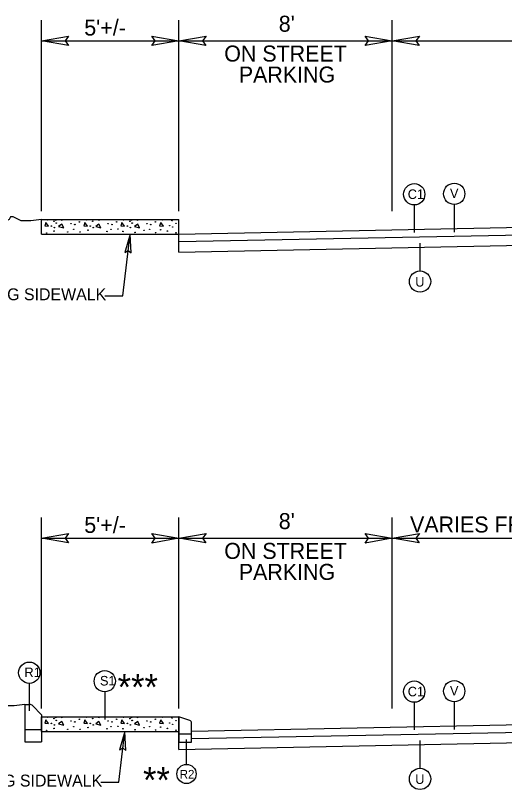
# Model space of a CAD drawing. Extents: x 1022283 to 1026986, y 174822 to 180471.
# Drawn here: x 1023136 to 1023625, y 178950 to 179724 of the extents above; entities that cross this region are included whole.
import ezdxf

# ---------------------------------------------------------------- set-up
doc = ezdxf.new("R2010")
doc.units = 0
for name, color, linetype in [('Default', 7, 'Continuous'), ('Prop Dimension', 7, 'Continuous'), ('Prop Terminator CELL', 7, 'Continuous'), ('Typical Curb CELL', 7, 'Continuous'), ('Typical ID Circle CELL', 7, 'Continuous'), ('Typical Slope Point Local CELL', 7, 'Continuous'), ('Typical Text General CELL', 7, 'Continuous'), ('Typical Text ID Circle CELL', 7, 'Continuous')]:
    doc.layers.add(name, color=color, linetype=linetype)

# ---------------------------------------------------------------- blocks, each defined once
blk = doc.blocks.new('Terminator')
at = {"layer": 'Prop Terminator CELL'}
blk.add_lwpolyline([(-9, 1.55), (0, 0), (-9.05, -1.6), (-7.9, 0)], close=True, dxfattribs=at)

msp = doc.modelspace()

# ---------------------------------------------------------------- linework, layer by layer
at = {"layer": 'Default'}
for p, q in [((1023162.42, 179527.88), (1023162.42, 179718.7)), ((1023299.79, 179527.88), (1023299.79, 179718.7)), ((1023512.98, 179527.88), (1023512.98, 179718.7)), ((1023162.42, 179698.14), (1023299.79, 179698.14)), ((1023162.42, 179698.14), (1023299.79, 179698.14)), ((1023299.79, 179698.14), (1023807.5, 179698.14)), ((1023162.42, 179527.88), (1023162.42, 179683.89)), ((1023162.42, 179527.88), (1023162.42, 179683.89)), ((1023162.42, 179030.88), (1023162.42, 179221.7)), ((1023299.79, 179030.88), (1023299.79, 179221.7)), ((1023512.98, 179030.88), (1023512.98, 179221.7)), ((1023162.42, 179201.13), (1023299.79, 179201.13)), ((1023162.42, 179201.13), (1023299.79, 179201.13)), ((1023299.79, 179201.13), (1023807.5, 179201.13)), ((1023162.42, 179030.88), (1023162.42, 179186.89)), ((1023162.42, 179030.88), (1023162.42, 179186.89))]:
    msp.add_line(p, q, dxfattribs=at)
at = {"layer": 'Prop Dimension'}
for p, q in [((1023299.79, 179505.09), (1023807.5, 179515.24)), ((1023299.79, 179505.09), (1023807.5, 179515.24)), ((1023299.79, 179497.58), (1023807.5, 179507.74)), ((1023299.79, 179497.58), (1023807.5, 179507.74)), ((1023243.88, 179443.37), (1023251.01, 179505.09)), ((1023299.79, 179487), (1023807.5, 179497.16)), ((1023225.73, 179443.37), (1023243.88, 179443.37)), ((1023312.45, 179008.34), (1023807.5, 179018.24)), ((1023312.45, 179008.34), (1023807.5, 179018.24)), ((1023312.45, 179000.84), (1023807.5, 179010.74)), ((1023312.45, 179000.84), (1023807.5, 179010.74)), ((1023239.83, 178957.41), (1023245.68, 179008.08)), ((1023299.79, 178990), (1023807.5, 179000.15)), ((1023221.68, 178957.41), (1023239.83, 178957.41))]:
    msp.add_line(p, q, dxfattribs=at)
at = {"layer": 'Prop Terminator CELL'}
for points in [[(1023189.42, 179693.49), (1023162.42, 179698.14), (1023189.57, 179702.94), (1023186.12, 179698.14)], [(1023189.42, 179693.49), (1023162.42, 179698.14), (1023189.57, 179702.94), (1023186.12, 179698.14)], [(1023272.79, 179702.79), (1023299.79, 179698.14), (1023272.64, 179693.34), (1023276.09, 179698.14)], [(1023272.79, 179702.79), (1023299.79, 179698.14), (1023272.64, 179693.34), (1023276.09, 179698.14)], [(1023326.79, 179693.49), (1023299.79, 179698.14), (1023326.94, 179702.94), (1023323.49, 179698.14)], [(1023485.98, 179702.79), (1023512.98, 179698.14), (1023485.83, 179693.34), (1023489.28, 179698.14)], [(1023539.98, 179693.49), (1023512.98, 179698.14), (1023540.13, 179702.94), (1023536.68, 179698.14)], [(1023189.42, 179196.48), (1023162.42, 179201.13), (1023189.57, 179205.93), (1023186.12, 179201.13)], [(1023189.42, 179196.48), (1023162.42, 179201.13), (1023189.57, 179205.93), (1023186.12, 179201.13)], [(1023272.79, 179205.78), (1023299.79, 179201.13), (1023272.64, 179196.33), (1023276.09, 179201.13)], [(1023272.79, 179205.78), (1023299.79, 179201.13), (1023272.64, 179196.33), (1023276.09, 179201.13)], [(1023326.79, 179196.48), (1023299.79, 179201.13), (1023326.94, 179205.93), (1023323.49, 179201.13)], [(1023485.98, 179205.78), (1023512.98, 179201.13), (1023485.83, 179196.33), (1023489.28, 179201.13)], [(1023539.98, 179196.48), (1023512.98, 179201.13), (1023540.13, 179205.93), (1023536.68, 179201.13)]]:
    msp.add_lwpolyline(points, close=True, dxfattribs=at)
at = {"layer": 'Typical Curb CELL'}
for p, q in [((1023162.42, 179519.61), (1023299.79, 179519.61)), ((1023162.42, 179505.09), (1023162.42, 179519.61)), ((1023162.42, 179519.61), (1023299.79, 179519.61)), ((1023162.42, 179505.09), (1023162.42, 179519.61)), ((1023166.92, 179516.7), (1023165.86, 179513.18)), ((1023166.92, 179516.7), (1023165.86, 179513.18)), ((1023169.57, 179512.98), (1023166.92, 179516.7)), ((1023169.57, 179512.98), (1023166.92, 179516.7)), ((1023182.65, 179514.95), (1023179.46, 179512.63)), ((1023182.65, 179514.95), (1023179.46, 179512.63)), ((1023184.59, 179511.4), (1023182.65, 179514.95)), ((1023184.59, 179511.4), (1023182.65, 179514.95)), ((1023205.65, 179516.7), (1023204.58, 179513.18)), ((1023205.65, 179516.7), (1023204.58, 179513.18)), ((1023208.33, 179512.98), (1023205.65, 179516.7)), ((1023208.33, 179512.98), (1023205.65, 179516.7)), ((1023219.82, 179514.95), (1023216.62, 179512.63)), ((1023219.82, 179514.95), (1023216.62, 179512.63)), ((1023221.76, 179511.4), (1023219.82, 179514.95)), ((1023221.76, 179511.4), (1023219.82, 179514.95)), ((1023242.81, 179516.7), (1023241.75, 179513.18)), ((1023242.81, 179516.7), (1023241.75, 179513.18)), ((1023245.46, 179512.98), (1023242.81, 179516.7)), ((1023245.46, 179512.98), (1023242.81, 179516.7)), ((1023258.54, 179514.95), (1023255.35, 179512.63)), ((1023258.54, 179514.95), (1023255.35, 179512.63)), ((1023260.48, 179511.4), (1023258.54, 179514.95)), ((1023260.48, 179511.4), (1023258.54, 179514.95)), ((1023281.54, 179516.7), (1023280.47, 179513.18)), ((1023281.54, 179516.7), (1023280.47, 179513.18)), ((1023284.22, 179512.98), (1023281.54, 179516.7)), ((1023284.22, 179512.98), (1023281.54, 179516.7)), ((1023299.79, 179487), (1023299.79, 179519.61)), ((1023299.79, 179509.27), (1023299.79, 179519.61)), ((1023299.79, 179487), (1023299.79, 179519.61)), ((1023299.79, 179509.27), (1023299.79, 179519.61)), ((1023165.86, 179513.18), (1023169.57, 179512.98)), ((1023165.86, 179513.18), (1023169.57, 179512.98)), ((1023179.46, 179512.63), (1023184.59, 179511.4)), ((1023179.46, 179512.63), (1023184.59, 179511.4)), ((1023204.58, 179513.18), (1023208.33, 179512.98)), ((1023204.58, 179513.18), (1023208.33, 179512.98)), ((1023216.62, 179512.63), (1023221.76, 179511.4)), ((1023216.62, 179512.63), (1023221.76, 179511.4)), ((1023241.75, 179513.18), (1023245.46, 179512.98)), ((1023241.75, 179513.18), (1023245.46, 179512.98)), ((1023255.35, 179512.63), (1023260.48, 179511.4)), ((1023255.35, 179512.63), (1023260.48, 179511.4)), ((1023280.47, 179513.18), (1023284.22, 179512.98)), ((1023280.47, 179513.18), (1023284.22, 179512.98)), ((1023299.79, 179488.61), (1023299.79, 179506.59)), ((1023299.79, 179488.61), (1023299.79, 179506.59)), ((1023162.42, 179505.09), (1023299.79, 179505.09)), ((1023145.75, 179035.11), (1023150.59, 179035.11)), ((1023145.75, 179035.11), (1023145.75, 179010.11)), ((1023162.42, 179024.69), (1023153.59, 179033.84)), ((1023162.42, 179024.69), (1023162.42, 179010.11)), ((1023162.42, 179022.61), (1023299.79, 179022.61)), ((1023162.42, 179008.08), (1023162.42, 179022.61)), ((1023162.42, 179022.61), (1023299.79, 179022.61)), ((1023162.42, 179008.08), (1023162.42, 179022.61)), ((1023166.92, 179019.69), (1023165.86, 179016.17)), ((1023166.92, 179019.69), (1023165.86, 179016.17)), ((1023169.57, 179015.98), (1023166.92, 179019.69)), ((1023169.57, 179015.98), (1023166.92, 179019.69)), ((1023205.65, 179019.69), (1023204.58, 179016.17)), ((1023205.65, 179019.69), (1023204.58, 179016.17)), ((1023208.33, 179015.98), (1023205.65, 179019.69)), ((1023208.33, 179015.98), (1023205.65, 179019.69)), ((1023242.81, 179019.69), (1023241.75, 179016.17)), ((1023242.81, 179019.69), (1023241.75, 179016.17)), ((1023245.46, 179015.98), (1023242.81, 179019.69)), ((1023245.46, 179015.98), (1023242.81, 179019.69)), ((1023281.54, 179019.69), (1023280.47, 179016.17)), ((1023281.54, 179019.69), (1023280.47, 179016.17)), ((1023284.22, 179015.98), (1023281.54, 179019.69)), ((1023284.22, 179015.98), (1023281.54, 179019.69)), ((1023299.79, 178990), (1023299.79, 179022.61)), ((1023299.79, 179012.27), (1023299.79, 179022.61)), ((1023299.79, 178990), (1023299.79, 179022.61)), ((1023299.79, 179012.27), (1023299.79, 179022.61)), ((1023310.77, 179018.95), (1023299.79, 179022.61)), ((1023299.79, 179022.61), (1023299.79, 179005.74)), ((1023165.86, 179016.17), (1023169.57, 179015.98)), ((1023165.86, 179016.17), (1023169.57, 179015.98)), ((1023182.65, 179017.95), (1023179.46, 179015.62)), ((1023182.65, 179017.95), (1023179.46, 179015.62)), ((1023179.46, 179015.62), (1023184.59, 179014.4)), ((1023179.46, 179015.62), (1023184.59, 179014.4)), ((1023184.59, 179014.4), (1023182.65, 179017.95)), ((1023184.59, 179014.4), (1023182.65, 179017.95)), ((1023204.58, 179016.17), (1023208.33, 179015.98)), ((1023204.58, 179016.17), (1023208.33, 179015.98)), ((1023219.82, 179017.95), (1023216.62, 179015.62)), ((1023219.82, 179017.95), (1023216.62, 179015.62)), ((1023216.62, 179015.62), (1023221.76, 179014.4)), ((1023216.62, 179015.62), (1023221.76, 179014.4)), ((1023221.76, 179014.4), (1023219.82, 179017.95)), ((1023221.76, 179014.4), (1023219.82, 179017.95)), ((1023241.75, 179016.17), (1023245.46, 179015.98)), ((1023241.75, 179016.17), (1023245.46, 179015.98)), ((1023258.54, 179017.95), (1023255.35, 179015.62)), ((1023258.54, 179017.95), (1023255.35, 179015.62)), ((1023255.35, 179015.62), (1023260.48, 179014.4)), ((1023255.35, 179015.62), (1023260.48, 179014.4)), ((1023260.48, 179014.4), (1023258.54, 179017.95)), ((1023260.48, 179014.4), (1023258.54, 179017.95)), ((1023280.47, 179016.17), (1023284.22, 179015.98)), ((1023280.47, 179016.17), (1023284.22, 179015.98)), ((1023312.45, 179005.74), (1023312.45, 179016.62)), ((1023145.75, 179010.24), (1023145.75, 178997.61)), ((1023145.75, 179010.11), (1023162.42, 179010.11)), ((1023162.42, 179010.24), (1023162.42, 178997.61)), ((1023162.42, 179008.08), (1023299.79, 179008.08)), ((1023299.79, 178991.6), (1023299.79, 179009.58)), ((1023299.79, 178991.6), (1023299.79, 179009.58)), ((1023299.79, 179005.74), (1023312.45, 179005.74)), ((1023299.79, 179005.74), (1023299.79, 178997.3)), ((1023312.45, 178997.3), (1023312.45, 179005.74)), ((1023145.75, 178997.61), (1023162.42, 178997.61)), ((1023299.79, 178997.3), (1023312.45, 178997.3))]:
    msp.add_line(p, q, dxfattribs=at)
for centre in [(1023168.52, 179519.19), (1023168.52, 179519.19), (1023174.89, 179517.95), (1023174.89, 179517.95), (1023176.63, 179519.01), (1023176.63, 179519.01), (1023177.16, 179516.01), (1023177.16, 179516.01), (1023182.64, 179519.01), (1023182.64, 179519.01), (1023191.85, 179515.47), (1023191.85, 179515.47), (1023195.74, 179514.59), (1023195.74, 179514.59), (1023200.35, 179517.25), (1023200.35, 179517.25), (1023207.25, 179519.19), (1023207.25, 179519.19), (1023213.62, 179517.95), (1023213.62, 179517.95), (1023219.8, 179519.01), (1023219.8, 179519.01), (1023229, 179515.47), (1023229, 179515.47), (1023232.9, 179514.59), (1023232.9, 179514.59), (1023237.5, 179517.25), (1023237.5, 179517.25), (1023244.41, 179519.19), (1023244.41, 179519.19), (1023250.78, 179517.95), (1023250.78, 179517.95), (1023252.52, 179519.01), (1023252.52, 179519.01), (1023253.05, 179516.01), (1023253.05, 179516.01), (1023258.53, 179519.01), (1023258.53, 179519.01), (1023267.74, 179515.47), (1023267.74, 179515.47), (1023271.63, 179514.59), (1023271.63, 179514.59), (1023276.24, 179517.25), (1023276.24, 179517.25), (1023283.14, 179519.19), (1023283.14, 179519.19), (1023290.51, 179513.53), (1023290.51, 179513.53), (1023292.99, 179518.49), (1023292.99, 179518.49), (1023296.93, 179515.81), (1023296.93, 179515.81), (1023167.62, 179506.11), (1023167.62, 179506.11), (1023172.41, 179513), (1023172.41, 179513), (1023175.05, 179508.05), (1023175.05, 179508.05), (1023175.39, 179511.58), (1023175.39, 179511.58), (1023188.74, 179507.08), (1023188.74, 179507.08), (1023194.68, 179509.81), (1023194.68, 179509.81), (1023201.01, 179507.08), (1023201.01, 179507.08), (1023208.89, 179508.96), (1023208.89, 179508.96), (1023211.14, 179513), (1023211.14, 179513), (1023214.12, 179511.58), (1023214.12, 179511.58), (1023227.82, 179507.66), (1023227.82, 179507.66), (1023231.84, 179509.81), (1023231.84, 179509.81), (1023238.8, 179510.18), (1023238.8, 179510.18), (1023243.77, 179507.66), (1023243.77, 179507.66), (1023248.3, 179513), (1023248.3, 179513), (1023251.28, 179511.58), (1023251.28, 179511.58), (1023255.98, 179506.69), (1023255.98, 179506.69), (1023264.96, 179508.76), (1023264.96, 179508.76), (1023270.57, 179509.81), (1023270.57, 179509.81), (1023276.39, 179506.44), (1023276.39, 179506.44), (1023281.5, 179509.34), (1023281.5, 179509.34), (1023288.34, 179508.05), (1023288.34, 179508.05), (1023293.49, 179512.11), (1023293.49, 179512.11), (1023296.93, 179506.31), (1023296.93, 179506.31), (1023168.52, 179022.19), (1023168.52, 179022.19), (1023174.89, 179020.95), (1023174.89, 179020.95), (1023176.63, 179022.01), (1023176.63, 179022.01), (1023177.16, 179019.01), (1023177.16, 179019.01), (1023182.64, 179022.01), (1023182.64, 179022.01), (1023191.85, 179018.47), (1023191.85, 179018.47), (1023200.35, 179020.24), (1023200.35, 179020.24), (1023207.25, 179022.19), (1023207.25, 179022.19), (1023213.62, 179020.95), (1023213.62, 179020.95), (1023219.8, 179022.01), (1023219.8, 179022.01), (1023229, 179018.47), (1023229, 179018.47), (1023237.5, 179020.24), (1023237.5, 179020.24), (1023244.41, 179022.19), (1023244.41, 179022.19), (1023250.78, 179020.95), (1023250.78, 179020.95), (1023252.52, 179022.01), (1023252.52, 179022.01), (1023253.05, 179019.01), (1023253.05, 179019.01), (1023258.53, 179022.01), (1023258.53, 179022.01), (1023267.74, 179018.47), (1023267.74, 179018.47), (1023276.24, 179020.24), (1023276.24, 179020.24), (1023283.14, 179022.19), (1023283.14, 179022.19), (1023292.99, 179021.49), (1023292.99, 179021.49), (1023296.93, 179018.8), (1023296.93, 179018.8), (1023172.41, 179015.99), (1023172.41, 179015.99), (1023175.05, 179011.05), (1023175.05, 179011.05), (1023175.39, 179014.58), (1023175.39, 179014.58), (1023194.68, 179012.81), (1023194.68, 179012.81), (1023195.74, 179017.59), (1023195.74, 179017.59), (1023208.89, 179011.95), (1023208.89, 179011.95), (1023211.14, 179015.99), (1023211.14, 179015.99), (1023214.12, 179014.58), (1023214.12, 179014.58), (1023227.82, 179010.66), (1023227.82, 179010.66), (1023231.84, 179012.81), (1023231.84, 179012.81), (1023232.9, 179017.59), (1023232.9, 179017.59), (1023238.8, 179013.18), (1023238.8, 179013.18), (1023243.77, 179010.66), (1023243.77, 179010.66), (1023248.3, 179015.99), (1023248.3, 179015.99), (1023251.28, 179014.58), (1023251.28, 179014.58), (1023264.96, 179011.76), (1023264.96, 179011.76), (1023270.57, 179012.81), (1023270.57, 179012.81), (1023271.63, 179017.59), (1023271.63, 179017.59), (1023281.5, 179012.34), (1023281.5, 179012.34), (1023288.34, 179011.05), (1023288.34, 179011.05), (1023290.51, 179016.53), (1023290.51, 179016.53), (1023293.49, 179015.11), (1023293.49, 179015.11), (1023167.62, 179009.11), (1023167.62, 179009.11), (1023188.74, 179010.08), (1023188.74, 179010.08), (1023201.01, 179010.08), (1023201.01, 179010.08), (1023255.98, 179009.69), (1023255.98, 179009.69), (1023276.39, 179009.43), (1023276.39, 179009.43), (1023296.93, 179009.3), (1023296.93, 179009.3)]:
    msp.add_circle(centre, 0.249, dxfattribs=at)
for centre, radius, start, end in [((1023150.59, 179030.94), 4.17, 43.9997, 90), ((1023309.99, 179016.62), 2.46, 0, 71.56505)]:
    msp.add_arc(centre, radius, start, end, dxfattribs=at)
at = {"layer": 'Typical ID Circle CELL'}
for p, q in [((1023534.91, 179534.22), (1023534.91, 179506.7)), ((1023574.86, 179534.64), (1023574.86, 179507.11)), ((1023540.73, 179468.31), (1023540.73, 179495.84)), ((1023150.26, 179056.04), (1023150.26, 179028.51)), ((1023225.67, 179047.62), (1023225.67, 179020.09)), ((1023534.91, 179037.22), (1023534.91, 179009.69)), ((1023574.86, 179037.63), (1023574.86, 179010.11)), ((1023307.34, 178975.15), (1023307.34, 178999.93)), ((1023540.73, 178971.31), (1023540.73, 178998.84))]:
    msp.add_line(p, q, dxfattribs=at)
for centre, radius in [((1023534.91, 179544.87), 10.65), ((1023574.86, 179545.28), 10.65), ((1023540.73, 179457.66), 10.65), ((1023150.26, 179066.69), 10.65), ((1023225.67, 179058.27), 10.65), ((1023534.91, 179047.87), 10.65), ((1023574.86, 179048.28), 10.65), ((1023307.34, 178965.57), 9.59), ((1023540.73, 178960.66), 10.65)]:
    msp.add_circle(centre, radius, dxfattribs=at)
at = {"layer": 'Typical Slope Point Local CELL'}
for points in [[(1023162.42, 179519.61), (1023151.65, 179518.27), (1023148.96, 179518.27), (1023144.91, 179518.27), (1023142.22, 179518.27), (1023139.52, 179519.61), (1023136.83, 179520.96), (1023134.14, 179522.32), (1023131.45, 179522.32), (1023130.09, 179519.61), (1023127.4, 179518.27), (1023124.71, 179516.92), (1023122.02, 179515.58), (1023119.32, 179515.58), (1023118.26, 179515.58)], [(1023162.42, 179519.61), (1023151.65, 179518.27), (1023148.96, 179518.27), (1023144.91, 179518.27), (1023142.22, 179518.27), (1023139.52, 179519.61), (1023136.83, 179520.96), (1023134.14, 179522.32), (1023131.45, 179522.32), (1023130.09, 179519.61), (1023127.4, 179518.27), (1023124.71, 179516.92), (1023122.02, 179515.58), (1023119.32, 179515.58), (1023118.26, 179515.58)], [(1023145.75, 179035.11), (1023134.98, 179033.77), (1023132.29, 179033.77), (1023128.25, 179033.77), (1023125.55, 179033.77), (1023122.86, 179035.11), (1023120.17, 179036.46), (1023117.47, 179037.81), (1023114.78, 179037.81), (1023113.43, 179035.11), (1023110.74, 179033.77), (1023108.04, 179032.42), (1023105.35, 179031.07), (1023102.66, 179031.07), (1023101.6, 179031.07)], [(1023145.75, 179035.11), (1023134.98, 179033.77), (1023132.29, 179033.77), (1023128.25, 179033.77), (1023125.55, 179033.77), (1023122.86, 179035.11), (1023120.17, 179036.46), (1023117.47, 179037.81), (1023114.78, 179037.81), (1023113.43, 179035.11), (1023110.74, 179033.77), (1023108.04, 179032.42), (1023105.35, 179031.07), (1023102.66, 179031.07), (1023101.6, 179031.07)]]:
    msp.add_lwpolyline(points, dxfattribs=at)

# ---------------------------------------------------------------- block references
at = {"layer": 'Prop Dimension', "xscale": 2.0767499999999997, "yscale": -2.076749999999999, "rotation": 83.4116733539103}
for p in [(1023251.01, 179505.09), (1023245.68, 179008.08)]:
    msp.add_blockref('Terminator', p, dxfattribs=at)

# ---------------------------------------------------------------- texts
at = {"layer": 'Prop Dimension'}
for s, p in [("8'", (1023399.56, 179707.27)), ("5'+/-", (1023205.17, 179703.4)), ('ON STREET', (1023345.07, 179677.47)), ('PARKING', (1023359.6, 179656.5)), ("5'+/-", (1023205.17, 179206.4)), ("8'", (1023399.56, 179210.26)), ("VARIES FROM 10' TO 14'", (1023530.73, 179206.85)), ('ON STREET', (1023345.07, 179180.47)), ('PARKING', (1023359.6, 179159.5))]:
    msp.add_text(s, height=16, dxfattribs=at).set_placement(p)
at = {"layer": 'Typical Slope Point Local CELL'}
for s, p in [('***', (1023238.52, 179039.52)), ('**', (1023263.9, 178946.63))]:
    msp.add_text(s, height=25.771, dxfattribs=at).set_placement(p)
at = {"layer": 'Typical Text General CELL'}
for p in [(1023066.22, 179438.94), (1023062.17, 178952.98)]:
    msp.add_text('EXISTING SIDEWALK', height=11.8979, dxfattribs=at).set_placement(p)
at = {"layer": 'Typical Text ID Circle CELL'}
for s, height, p in [('C1', 9.534, (1023528.44, 179540.14)), ('V', 9.53, (1023570.63, 179540.98)), ('U', 9.53, (1023535.91, 179452.6)), ('R1', 9.534, (1023145.39, 179062.38)), ('S1', 9.534, (1023220.87, 179053.96)), ('C1', 9.534, (1023528.44, 179043.14)), ('V', 9.53, (1023570.63, 179043.98)), ('R2', 8.581, (1023300.55, 178961.01)), ('U', 9.53, (1023535.91, 178955.6))]:
    msp.add_text(s, height=height, dxfattribs=at).set_placement(p)

doc.saveas('drawing.dxf')
